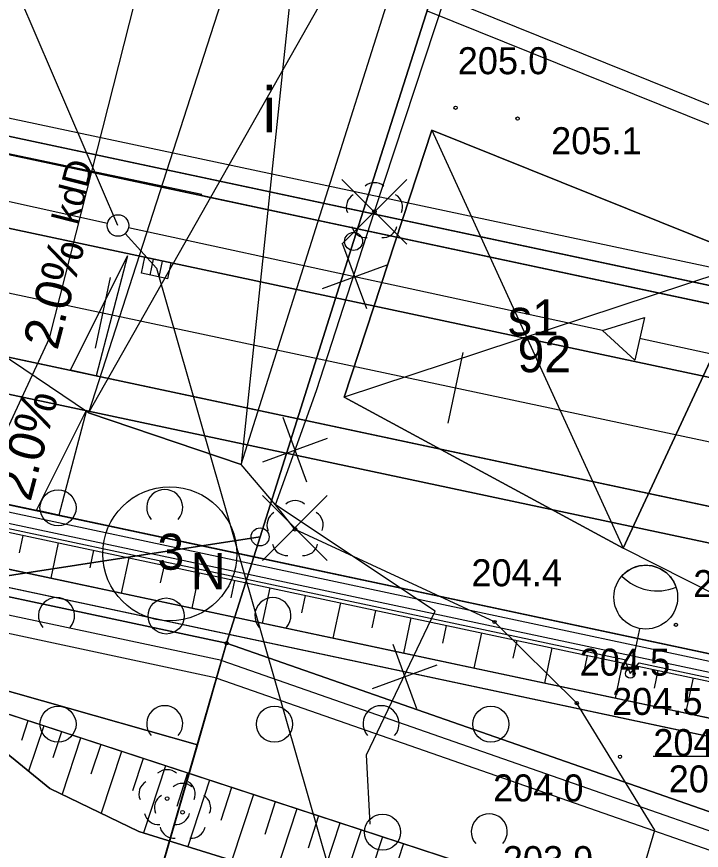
# Model space of a CAD drawing. Extents: x 6512606 to 6513006, y 6022524 to 6022728.
# Drawn here: x 6512774.88 to 6512793.86, y 6022575.27 to 6022598.41 of the extents above; entities that cross this region are included whole.
import ezdxf

# ---------------------------------------------------------------- set-up
doc = ezdxf.new("R2010")
doc.units = 0
for name, color, linetype in [('000 Inne (niezydentyfikowane)', 7, 'Continuous'), ('20', 7, 'Continuous'), ('202-punkt graniczny', 7, 'Continuous'), ('203-punkt graniczny', 7, 'Continuous'), ('210-oznaczenie konturu użytku gruntowego', 7, 'Continuous'), ('211-numer działki ewidencyjnej', 7, 'Continuous'), ('216-obręb ewidencyjny', 7, 'Continuous'), ('217-kontur klasyfikacyjny', 7, 'Continuous'), ('218-kontur użytku gruntowego', 7, 'Continuous'), ('219-działka ewidencyjna', 7, 'Continuous'), ('312-budynek ewidencyjny', 7, 'Continuous'), ('312-oznaczenie budynku ewidencyjnego', 7, 'Continuous'), ('312-oznaczenie budynku ewidencyjnego-Atr117', 7, 'Continuous'), ('4', 7, 'Continuous'), ('6', 7, 'Continuous'), ('996-Tekst dodatkowy mały', 7, 'Continuous'), ('budynek', 7, 'Continuous'), ('Default', 7, 'Continuous'), ('drzewo liściaste', 7, 'Continuous'), ('E_OSW_KABLE', 7, 'Continuous'), ('E_OSW_LAMPA', 7, 'Continuous'), ('kolor_kostka_bet', 7, 'Continuous'), ('kolor_sc_rowerowa', 7, 'Continuous'), ('kolor_skarpa umocniona', 7, 'Continuous'), ('Level 60', 7, 'Continuous'), ('maxp_bariera_ochronna', 7, 'Continuous'), ('maxp_inst_energ', 7, 'Continuous'), ('maxp_kan_deszczowa', 7, 'Continuous'), ('maxp_kratki', 7, 'Continuous'), ('maxp_krawężnik', 7, 'Continuous'), ('maxp_likwidacje', 7, 'Continuous'), ('maxp_obrzeże', 7, 'Continuous'), ('maxp_os', 7, 'Continuous'), ('maxp_przechyłki', 7, 'Continuous'), ('maxp_ramka_2', 7, 'Continuous'), ('maxp_skarpa', 7, 'Continuous'), ('ogrodzenie', 7, 'Continuous'), ('ogrodzenie trwałe', 7, 'Continuous'), ('pikieta naturalna', 7, 'Continuous'), ('pikieta naturalna-Atr2', 7, 'Continuous'), ('przewód kanalizacyjny (linia)', 7, 'Continuous'), ('przewód kanalizacyjny (linia)-Atr1', 7, 'Continuous'), ('punkt wysokościowy naturalny', 7, 'Continuous'), ('punkt wysokościowy naturalny-Atr2', 7, 'Continuous'), ('rzedna-Atr2', 7, 'Continuous'), ('skarpa nieumocniona', 7, 'Continuous'), ('woda stojąca', 7, 'Continuous'), ('zadrzewienie  zakrzewienie', 7, 'Continuous')]:
    doc.layers.add(name, color=color, linetype=linetype)

# ---------------------------------------------------------------- blocks, each defined once
blk = doc.blocks.new('202')
at = {"layer": 'Default'}
blk.add_circle((0, 0), 2.5, dxfattribs=at)
blk = doc.blocks.new('203')
at = {"layer": 'Default'}
blk.add_circle((0, 0), 0.45, dxfattribs=at)
blk = doc.blocks.new('PW01')
at = {"layer": 'Default'}
blk.add_circle((0, 0), 0.45, dxfattribs=at)
blk = doc.blocks.new('OP021')
at = {"layer": 'Default'}
blk.add_circle((0, 0), 0.5, dxfattribs=at)
for centre, start, end in [((0, 4), 49.272, 130.728), ((-3.8, 1.24), 121.308, 202.548), ((3.8, 1.24), 337.452, 58.692), ((-2.35, -3.24), 193.221, 274.871), ((2.35, -3.24), 265.129, 346.779)]:
    blk.add_arc(centre, 4, start, end, dxfattribs=at)
blk = doc.blocks.new('OTZK1')
at = {"layer": 'Default'}
blk.add_circle((0, 0), 5, dxfattribs=at)
blk = doc.blocks.new('OTZK2')
at = {"layer": 'Default'}
blk.add_arc((0, 0), 5, 318.85, 221.162, dxfattribs=at)

msp = doc.modelspace()

# ---------------------------------------------------------------- linework, layer by layer
msp.add_line((6512749.181, 6022600.515), (6512804.476, 6022588.74))
at = {"layer": '000 Inne (niezydentyfikowane)'}
for points in [[(6512775.19, 6022578.87), (6512775.01, 6022578.32)], [(6512775.63, 6022578.73), (6512775.21, 6022577.47)], [(6512776.12, 6022578.56), (6512775.88, 6022577.84)], [(6512776.65, 6022578.39), (6512776.14, 6022576.83)], [(6512777.21, 6022578.21), (6512776.94, 6022577.39)], [(6512777.79, 6022578.02), (6512777.22, 6022576.3)], [(6512778.39, 6022577.82), (6512778.09, 6022576.92)], [(6512779.01, 6022577.62), (6512778.4, 6022575.76)], [(6512779.62, 6022577.42), (6512779.32, 6022576.49)], [(6512780.23, 6022577.22), (6512779.63, 6022575.38)], [(6512780.84, 6022577.02), (6512780.54, 6022576.1)], [(6512781.45, 6022576.82), (6512780.85, 6022575)], [(6512782.05, 6022576.62), (6512781.76, 6022575.71)], [(6512782.65, 6022576.42), (6512782.06, 6022574.62)], [(6512783.25, 6022576.23), (6512782.96, 6022575.33)], [(6512783.84, 6022576.03), (6512783.26, 6022574.25)], [(6512784.43, 6022575.84), (6512784.14, 6022574.95)], [(6512785.02, 6022575.65), (6512784.44, 6022573.88)], [(6512785.61, 6022575.46), (6512785.32, 6022574.58)]]:
    msp.add_lwpolyline(points, dxfattribs=at)
at = {"layer": '20'}
for p, q in [((6512777.689, 6022592.612), (6512773.476, 6022602.425)), ((6512778.758, 6022591.427), (6512784.26, 6022572.235))]:
    msp.add_line(p, q, dxfattribs=at)
at = {"layer": '216-obręb ewidencyjny'}
for points in [[(6512728.286, 6022540.131), (6512737.69, 6022552.74), (6512751.08, 6022569.37), (6512775.81, 6022564.08), (6512780.7, 6022581.02), (6512806.2, 6022572.11), (6512806.62, 6022563.51), (6512811.41, 6022558.95), (6512818.47, 6022559.72), (6512828.23, 6022562.62), (6512858.85, 6022571.74), (6512855.78, 6022583.95), (6512853.17, 6022604.51), (6512852.25, 6022608.25), (6512838.47, 6022634.29)], [(6512824.714, 6022553.406), (6512818.47, 6022559.72), (6512811.41, 6022558.95), (6512806.62, 6022563.51), (6512806.2, 6022572.11), (6512780.7, 6022581.02), (6512775.81, 6022564.08), (6512751.08, 6022569.37)]]:
    msp.add_lwpolyline(points, dxfattribs=at)
at = {"layer": '217-kontur klasyfikacyjny'}
for points in [[(6512784.22, 6022592.17), (6512791.71, 6022615.65)], [(6512781.63, 6022583.97), (6512784.22, 6022592.17)], [(6512773.05, 6022582.65), (6512781.63, 6022583.97)]]:
    msp.add_lwpolyline(points, dxfattribs=at)
at = {"layer": '218-kontur użytku gruntowego'}
for points in [[(6512791.71, 6022615.65), (6512784.22, 6022592.17)], [(6512784.22, 6022592.17), (6512791.71, 6022615.65)], [(6512784.22, 6022592.17), (6512781.63, 6022583.97)], [(6512781.63, 6022583.97), (6512784.22, 6022592.17)], [(6512781.63, 6022583.97), (6512773.05, 6022582.65)], [(6512773.05, 6022582.65), (6512781.63, 6022583.97)], [(6512780.7, 6022581.02), (6512781.63, 6022583.97)], [(6512781.63, 6022583.97), (6512780.7, 6022581.02)], [(6512773.05, 6022582.65), (6512780.7, 6022581.02)], [(6512780.7, 6022581.02), (6512773.05, 6022582.65)], [(6512779.89, 6022578.2), (6512780.7, 6022581.02)], [(6512780.7, 6022581.02), (6512779.89, 6022578.2)], [(6512780.7, 6022581.02), (6512806.2, 6022572.11)], [(6512806.2, 6022572.11), (6512780.7, 6022581.02)], [(6512771.29, 6022580.64), (6512779.89, 6022578.2)], [(6512779.89, 6022578.2), (6512771.29, 6022580.64)], [(6512775.81, 6022564.08), (6512779.89, 6022578.2)], [(6512779.89, 6022578.2), (6512775.81, 6022564.08)]]:
    msp.add_lwpolyline(points, dxfattribs=at)
at = {"layer": '219-działka ewidencyjna'}
for points in [[(6512791.71, 6022615.65), (6512784.22, 6022592.17)], [(6512784.22, 6022592.17), (6512781.63, 6022583.97)], [(6512781.63, 6022583.97), (6512773.05, 6022582.65)], [(6512781.63, 6022583.97), (6512780.7, 6022581.02)], [(6512780.7, 6022581.02), (6512773.05, 6022582.65)], [(6512780.7, 6022581.02), (6512775.81, 6022564.08)], [(6512780.7, 6022581.02), (6512806.2, 6022572.11)]]:
    msp.add_lwpolyline(points, dxfattribs=at)
at = {"layer": '312-budynek ewidencyjny'}
msp.add_lwpolyline([(6512783.96, 6022587.85), (6512786.39, 6022595.26), (6512795.4, 6022591.63), (6512791.7, 6022583.66)], close=True, dxfattribs=at)
at = {"layer": '4'}
for points in [[(6512791.71, 6022615.65), (6512784.22, 6022592.17)], [(6512784.22, 6022592.17), (6512781.63, 6022583.97)], [(6512781.63, 6022583.97), (6512773.05, 6022582.65)], [(6512781.63, 6022583.97), (6512780.7, 6022581.02)], [(6512780.7, 6022581.02), (6512773.05, 6022582.65)], [(6512780.7, 6022581.02), (6512775.81, 6022564.08)], [(6512780.7, 6022581.02), (6512806.2, 6022572.11)]]:
    msp.add_lwpolyline(points, dxfattribs=at)
at = {"layer": '6'}
msp.add_circle((6512779.124, 6022583.5), 1.859, dxfattribs=at)
at = {"layer": 'budynek'}
msp.add_lwpolyline([(6512776.87, 6022587.41), (6512781.1, 6022585.98), (6512787.49, 6022606.19), (6512783.36, 6022607.54)], close=True, dxfattribs=at)
at = {"layer": 'E_OSW_KABLE'}
for points in [[(6512761.962, 6022586.567), (6512762.264, 6022586.84), (6512791.737, 6022580.564), (6512791.895, 6022580.179)], [(6512791.895, 6022580.179), (6512792.146, 6022580.477), (6512819.749, 6022574.599), (6512820.082, 6022574.17)]]:
    msp.add_lwpolyline(points, dxfattribs=at)
at = {"layer": 'E_OSW_LAMPA'}
msp.add_line((6512792.147, 6022581.423), (6512791.921, 6022580.309), dxfattribs=at)
for centre, radius in [((6512792.324, 6022582.298), 0.885), ((6512791.895, 6022580.179), 0.132)]:
    msp.add_circle(centre, radius, dxfattribs=at)
for centre, radius, start, end in [((6512792.324, 6022582.298), 0.885, 18.4482, 138.4482), ((6512792.638, 6022583.834), 1.362, 224.2189, 292.6775)]:
    msp.add_arc(centre, radius, start, end, dxfattribs=at)
at = {"layer": 'kolor_kostka_bet'}
for p, q in [((6512804.476, 6022588.74), (6512749.181, 6022600.515)), ((6512748.908, 6022600.062), (6512804.444, 6022588.236)), ((6512804.444, 6022588.236), (6512748.908, 6022600.062)), ((6512810.802, 6022584.837), (6512749.708, 6022597.847)), ((6512749.708, 6022597.847), (6512810.802, 6022584.837)), ((6512806.649, 6022582.142), (6512751.029, 6022593.987)), ((6512747.886, 6022593.634), (6512811.17, 6022580.157)), ((6512812.638, 6022576.778), (6512745.389, 6022591.098))]:
    msp.add_line(p, q, dxfattribs=at)
for points in [[(6512751.029, 6022593.987), (6512751.029, 6022593.987), (6512806.649, 6022582.142)], [(6512773.05, 6022582.65), (6512780.7, 6022581.02), (6512806.2, 6022572.11), (6512806.62, 6022563.51), (6512855.78, 6022583.95)], [(6512773.05, 6022582.65), (6512780.7, 6022581.02), (6512806.2, 6022572.11), (6512806.62, 6022563.51), (6512855.78, 6022583.95)]]:
    msp.add_lwpolyline(points, dxfattribs=at)
at = {"layer": 'kolor_sc_rowerowa'}
for p, q in [((6512811.17, 6022580.157), (6512747.886, 6022593.634)), ((6512745.389, 6022591.098), (6512812.638, 6022576.778))]:
    msp.add_line(p, q, dxfattribs=at)
at = {"layer": 'kolor_skarpa umocniona'}
msp.add_line((6512795.384, 6022578.662), (6512793.428, 6022579.079), dxfattribs=at)
for points in [[(6512762.13, 6022585.744), (6512762.026, 6022585.255), (6512812.885, 6022574.424)], [(6512762.026, 6022585.255), (6512762.13, 6022585.744), (6512812.99, 6022574.913), (6512812.885, 6022574.424), (6512762.119, 6022585.235)], [(6512781.691, 6022581.578), (6512779.735, 6022581.995), (6512777.779, 6022582.412), (6512775.823, 6022582.828), (6512773.867, 6022583.245)], [(6512789.516, 6022579.912), (6512787.56, 6022580.329), (6512785.604, 6022580.745), (6512783.648, 6022581.162), (6512781.691, 6022581.578)], [(6512793.428, 6022579.079), (6512791.472, 6022579.496), (6512789.516, 6022579.912)]]:
    msp.add_lwpolyline(points, dxfattribs=at)
at = {"layer": 'Level 60'}
for points in [[(6512777.47, 6022591.168), (6512777.053, 6022589.212)], [(6512787.25, 6022589.085), (6512786.834, 6022587.129)]]:
    msp.add_lwpolyline(points, dxfattribs=at)
at = {"layer": 'maxp_bariera_ochronna'}
msp.add_line((6512753.108, 6022588.943), (6512815.82, 6022575.589), dxfattribs=at)
at = {"layer": 'maxp_inst_energ'}
msp.add_line((6512747.273, 6022590.493), (6512828.214, 6022573.256), dxfattribs=at)
at = {"layer": 'maxp_kan_deszczowa'}
for p, q in [((6512763.297, 6022595.797), (6512777.396, 6022592.677)), ((6512778.757, 6022591.428), (6512777.889, 6022592.389)), ((6512791.129, 6022589.696), (6512777.982, 6022592.549)), ((6512807.246, 6022586.199), (6512792.155, 6022589.473))]:
    msp.add_line(p, q, dxfattribs=at)
for points in [[(6512804.444, 6022588.236), (6512787.447, 6022591.855), (6512780, 6022593.441), (6512780.016, 6022593.468), (6512767.827, 6022596.033), (6512755.283, 6022598.704), (6512748.908, 6022600.062), (6512739.241, 6022611.647)], [(6512758.625, 6022588.28), (6512762.073, 6022587.546), (6512765.286, 6022586.861), (6512765.973, 6022586.715), (6512765.973, 6022586.715), (6512774.484, 6022584.902), (6512777.76, 6022584.205), (6512780.581, 6022583.604), (6512783.708, 6022582.938), (6512788.205, 6022581.98), (6512793.287, 6022580.898), (6512793.287, 6022580.898), (6512798.168, 6022579.859)]]:
    msp.add_lwpolyline(points, dxfattribs=at)
msp.add_lwpolyline([(6512792.024, 6022588.878), (6512791.129, 6022589.696), (6512792.285, 6022590.062)], close=True, dxfattribs=at)
msp.add_circle((6512777.689, 6022592.612), 0.3, dxfattribs=at)
at = {"layer": 'maxp_kratki'}
for p, q in [((6512778.338, 6022591.29), (6512778.432, 6022591.73)), ((6512778.338, 6022591.29), (6512778.432, 6022591.73)), ((6512779.165, 6022591.574), (6512778.432, 6022591.73)), ((6512779.165, 6022591.574), (6512778.432, 6022591.73)), ((6512778.583, 6022591.238), (6512778.677, 6022591.678)), ((6512778.583, 6022591.238), (6512778.677, 6022591.678)), ((6512778.827, 6022591.186), (6512778.922, 6022591.625)), ((6512778.827, 6022591.186), (6512778.922, 6022591.625)), ((6512779.071, 6022591.134), (6512779.165, 6022591.574)), ((6512779.071, 6022591.134), (6512779.165, 6022591.574)), ((6512779.071, 6022591.134), (6512778.338, 6022591.29)), ((6512779.071, 6022591.134), (6512778.338, 6022591.29))]:
    msp.add_line(p, q, dxfattribs=at)
at = {"layer": 'maxp_krawężnik'}
for p, q in [((6512749.708, 6022597.847), (6512811.419, 6022584.705)), ((6512751.029, 6022593.987), (6512811.378, 6022581.136))]:
    msp.add_line(p, q, dxfattribs=at)
at = {"layer": 'maxp_likwidacje'}
for p, q in [((6512783.36, 6022607.54), (6512781.1, 6022585.98)), ((6512787.49, 6022606.19), (6512776.87, 6022587.41)), ((6512786.39, 6022595.26), (6512791.7, 6022583.66)), ((6512783.898, 6022592.093), (6512785.698, 6022593.893)), ((6512785.698, 6022592.093), (6512783.898, 6022593.893)), ((6512784.585, 6022590.296), (6512783.928, 6022592.089)), ((6512783.36, 6022590.864), (6512785.153, 6022591.521)), ((6512795.4, 6022591.63), (6512783.96, 6022587.85)), ((6512782.928, 6022585.487), (6512782.272, 6022587.28)), ((6512781.704, 6022586.055), (6512783.496, 6022586.711)), ((6512781.693, 6022583.32), (6512783.493, 6022585.12)), ((6512783.493, 6022583.32), (6512781.693, 6022585.12)), ((6512785.975, 6022579.195), (6512785.318, 6022580.988)), ((6512784.75, 6022579.763), (6512786.543, 6022580.42))]:
    msp.add_line(p, q, dxfattribs=at)
msp.add_lwpolyline([(6512783.36, 6022607.54), (6512776.871, 6022587.41), (6512781.1, 6022585.98), (6512787.49, 6022606.19)], dxfattribs=at)
msp.add_lwpolyline([(6512795.4, 6022591.63), (6512786.39, 6022595.26), (6512783.96, 6022587.85), (6512791.7, 6022583.66)], close=True, dxfattribs=at)
at = {"layer": 'maxp_obrzeże'}
for p, q in [((6512747.886, 6022593.634), (6512811.17, 6022580.157)), ((6512745.389, 6022591.098), (6512812.638, 6022576.778))]:
    msp.add_line(p, q, dxfattribs=at)
at = {"layer": 'maxp_os'}
msp.add_line((6512747.611, 6022596.504), (6512812.444, 6022582.698), dxfattribs=at)
at = {"layer": 'maxp_przechyłki'}
for points in [[(6512777.079, 6022588.445), (6512776.37, 6022588.599), (6512777.954, 6022591.769)], [(6512776.051, 6022584.574), (6512775.43, 6022584.709), (6512776.817, 6022587.485)]]:
    msp.add_lwpolyline(points, close=True, dxfattribs=at)
at = {"layer": 'maxp_ramka_2'}
for p, q in [((6512749.285, 6022601.004), (6512804.509, 6022589.244)), ((6512780.565, 6022580.538), (6512746.303, 6022587.838)), ((6512780.43, 6022580.055), (6512746.53, 6022587.278))]:
    msp.add_line(p, q, dxfattribs=at)
for points in [[(6512799.94, 6022590.728), (6512800.503, 6022593.371), (6512786.88, 6022598.864)], [(6512786.263, 6022598.573), (6512799.926, 6022593.065), (6512799.451, 6022590.832)], [(6512780.565, 6022580.538), (6512805.717, 6022571.749), (6512806.155, 6022562.774)], [(6512780.43, 6022580.055), (6512805.234, 6022571.388), (6512805.691, 6022562.037)]]:
    msp.add_lwpolyline(points, dxfattribs=at)
at = {"layer": 'maxp_skarpa'}
for p, q in [((6512753.056, 6022588.699), (6512817.11, 6022575.058)), ((6512762.13, 6022585.744), (6512812.99, 6022574.913)), ((6512775.053, 6022584.014), (6512774.949, 6022583.525)), ((6512776.031, 6022583.806), (6512775.823, 6022582.828)), ((6512777.009, 6022583.598), (6512776.905, 6022583.109)), ((6512777.987, 6022583.39), (6512777.779, 6022582.412)), ((6512778.965, 6022583.181), (6512778.861, 6022582.692)), ((6512779.944, 6022582.973), (6512779.735, 6022581.995)), ((6512780.922, 6022582.765), (6512780.817, 6022582.276)), ((6512781.9, 6022582.556), (6512781.691, 6022581.578)), ((6512782.878, 6022582.348), (6512782.774, 6022581.859)), ((6512783.856, 6022582.14), (6512783.648, 6022581.162)), ((6512784.834, 6022581.932), (6512784.73, 6022581.443)), ((6512785.812, 6022581.723), (6512785.604, 6022580.745)), ((6512786.79, 6022581.515), (6512786.686, 6022581.026)), ((6512787.768, 6022581.307), (6512787.56, 6022580.329)), ((6512788.746, 6022581.098), (6512788.642, 6022580.609)), ((6512789.724, 6022580.89), (6512789.516, 6022579.912)), ((6512790.702, 6022580.682), (6512790.598, 6022580.193)), ((6512791.68, 6022580.474), (6512791.472, 6022579.496)), ((6512792.658, 6022580.265), (6512792.554, 6022579.776)), ((6512793.636, 6022580.057), (6512793.428, 6022579.079))]:
    msp.add_line(p, q, dxfattribs=at)
at = {"layer": 'ogrodzenie'}
msp.add_line((6512748.908, 6022600.062), (6512804.444, 6022588.236), dxfattribs=at)
at = {"layer": 'ogrodzenie trwałe'}
for points in [[(6512784.68, 6022576), (6512784.58, 6022577.92), (6512786.48, 6022581.91), (6512782.06, 6022584.86), (6512783.19, 6022588.03), (6512784.8, 6022593), (6512788.43, 6022604.01)], [(6512797.99, 6022580.48), (6512791.7, 6022583.66)]]:
    msp.add_lwpolyline(points, dxfattribs=at)
at = {"layer": 'przewód kanalizacyjny (linia)'}
msp.add_lwpolyline([(6512771.21, 6022579.63), (6512775.79, 6022589.49), (6512780.81, 6022609.27), (6512784.81, 6022621.53)], dxfattribs=at)
at = {"layer": 'rzedna-Atr2'}
msp.add_lwpolyline([(6512796.22, 6022576.49), (6512795.7, 6022577.88), (6512792.533, 6022577.88)], dxfattribs=at)
at = {"layer": 'skarpa nieumocniona'}
msp.add_lwpolyline([(6512771.62, 6022580.04), (6512772.41, 6022579.75), (6512775.8, 6022576.99), (6512778.27, 6022575.8), (6512788.79, 6022572.53), (6512793.8, 6022570.72), (6512792, 6022573.89), (6512788.89, 6022574.38)], close=True, dxfattribs=at)
msp.add_lwpolyline([(6512771.62, 6022580.04), (6512772.41, 6022579.75), (6512775.8, 6022576.99), (6512778.27, 6022575.8), (6512788.79, 6022572.53), (6512793.8, 6022570.72), (6512792, 6022573.89), (6512788.89, 6022574.38)], close=True, dxfattribs=at)
at = {"layer": 'woda stojąca'}
msp.add_lwpolyline([(6512822.08, 6022551.38), (6512805.27, 6022559.18), (6512802.35, 6022567.67), (6512799.36, 6022570.79), (6512795.57, 6022571.66), (6512793.8, 6022570.72), (6512788.79, 6022572.53), (6512778.27, 6022575.8), (6512775.8, 6022576.99), (6512772.41, 6022579.75), (6512771.62, 6022580.04), (6512770.3, 6022579.81), (6512769.49, 6022580.02), (6512768.52, 6022578.94)], dxfattribs=at)
at = {"layer": 'zadrzewienie  zakrzewienie'}
msp.add_lwpolyline([(6512757.57, 6022561.69), (6512765.47, 6022568.01), (6512770.86, 6022573.28), (6512769.34, 6022577.71), (6512768.52, 6022578.94), (6512769.49, 6022580.02), (6512770.3, 6022579.81), (6512771.62, 6022580.04), (6512773.43, 6022579.45), (6512788.89, 6022574.38), (6512792, 6022573.89), (6512792.58, 6022575.83), (6512790.41, 6022579.36), (6512788.13, 6022581.61), (6512782.6, 6022584.18), (6512782.06, 6022584.86), (6512781.1, 6022585.98), (6512776.87, 6022587.41), (6512770, 6022592.05), (6512764.51, 6022594.96), (6512748.08, 6022603.68)], dxfattribs=at)

# ---------------------------------------------------------------- block references
at = {"layer": '202-punkt graniczny', "xscale": 0.1, "yscale": 0.10000000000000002}
for p in [(6512784.22, 6022592.17), (6512781.63, 6022583.97)]:
    msp.add_blockref('202', p, dxfattribs=at)
at = {"layer": '203-punkt graniczny', "xscale": 0.1, "yscale": 0.10000000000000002}
msp.add_blockref('203', (6512780.7, 6022581.02), dxfattribs=at)
at = {"layer": 'drzewo liściaste', "xscale": 0.1, "yscale": 0.10000000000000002}
for p in [(6512784.8, 6022593), (6512782.6, 6022584.18), (6512779.05, 6022576.71), (6512779.48, 6022576.33)]:
    msp.add_blockref('OP021', p, dxfattribs=at)
at = {"layer": 'pikieta naturalna', "xscale": 0.1, "yscale": 0.10000000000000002}
for p in [(6512788.77, 6022595.58), (6512788.13, 6022581.61), (6512793.16, 6022581.53), (6512790.41, 6022579.36), (6512791.61, 6022577.87)]:
    msp.add_blockref('PW01', p, dxfattribs=at)
at = {"layer": 'punkt wysokościowy naturalny', "xscale": 0.1, "yscale": 0.10000000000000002}
msp.add_blockref('PW01', (6512787.05, 6022595.88), dxfattribs=at)
at = {"layer": 'zadrzewienie  zakrzewienie', "xscale": 0.1, "yscale": 0.10000000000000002}
for name, p in [('OTZK1', (6512776.026, 6022584.776)), ('OTZK2', (6512778.984, 6022584.787)), ('OTZK2', (6512775.984, 6022581.787)), ('OTZK1', (6512779.026, 6022581.776)), ('OTZK2', (6512781.984, 6022581.787)), ('OTZK1', (6512776.026, 6022578.776)), ('OTZK2', (6512778.984, 6022578.787)), ('OTZK1', (6512782.026, 6022578.776)), ('OTZK2', (6512784.984, 6022578.787)), ('OTZK1', (6512788.026, 6022578.776)), ('OTZK1', (6512785.026, 6022575.776)), ('OTZK2', (6512787.984, 6022575.787))]:
    msp.add_blockref(name, p, dxfattribs=at)

# ---------------------------------------------------------------- texts
at = {"layer": '210-oznaczenie konturu użytku gruntowego'}
msp.add_text('N', height=1, dxfattribs=at).set_placement((6512779.71, 6022582.52))
at = {"layer": '211-numer działki ewidencyjnej'}
msp.add_text('3', height=1, dxfattribs=at).set_placement((6512778.78, 6022583.06))
at = {"layer": '312-oznaczenie budynku ewidencyjnego'}
msp.add_text('92', height=1, dxfattribs=at).set_placement((6512788.77, 6022588.54))
at = {"layer": '312-oznaczenie budynku ewidencyjnego-Atr117'}
msp.add_text('s1', height=1, dxfattribs=at).set_placement((6512788.501, 6022589.56))
at = {"layer": '4'}
msp.add_text('3', height=1, dxfattribs=at).set_placement((6512778.78, 6022583.06))
at = {"layer": '996-Tekst dodatkowy mały'}
msp.add_text('i', height=1.25, dxfattribs=at).set_placement((6512781.7, 6022595.2))
at = {"layer": 'maxp_przechyłki'}
for p in [(6512776.006, 6022589.127), (6512775.261, 6022584.925)]:
    msp.add_text('2.0%', height=1, rotation=75.2497, dxfattribs=at).set_placement(p)
at = {"layer": 'pikieta naturalna-Atr2'}
for s, p in [('205.1', (6512789.7, 6022594.59)), ('204.4', (6512787.49, 6022582.6)), ('205.0', (6512793.64, 6022582.3)), ('204.5', (6512790.49, 6022580.12)), ('204.5', (6512791.39, 6022579.03)), ('204.2', (6512792.96, 6022576.88)), ('204.0', (6512788.09, 6022576.63))]:
    msp.add_text(s, height=0.75, dxfattribs=at).set_placement(p)
at = {"layer": 'przewód kanalizacyjny (linia)-Atr1'}
msp.add_text('kdD', height=0.75, rotation=75.759, dxfattribs=at).set_placement((6512776.58, 6022592.6))
at = {"layer": 'punkt wysokościowy naturalny-Atr2'}
for s, p in [('205.0', (6512787.11, 6022596.81)), ('203.9', (6512788.36, 6022574.64))]:
    msp.add_text(s, height=0.75, dxfattribs=at).set_placement(p)
at = {"layer": 'rzedna-Atr2'}
msp.add_text('204.05', height=0.75, dxfattribs=at).set_placement((6512792.533, 6022577.888))

doc.saveas('drawing.dxf')
